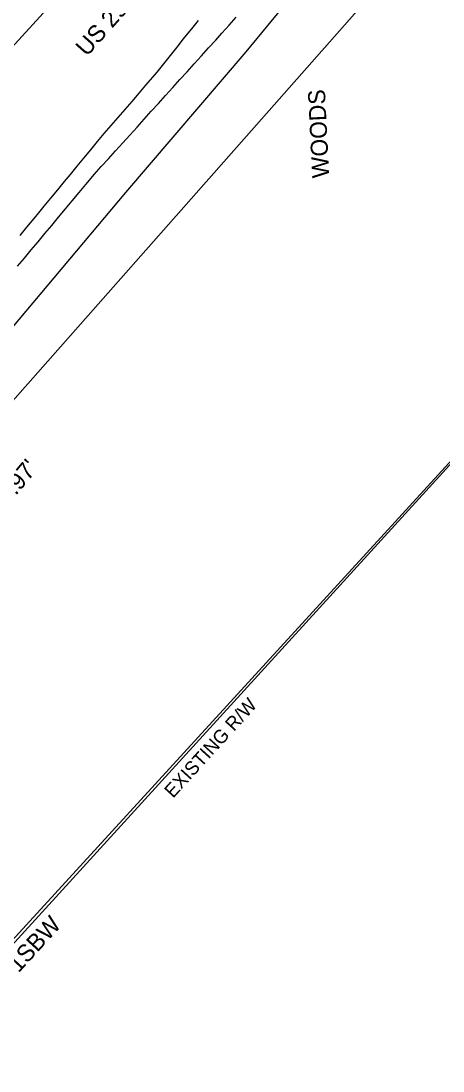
# Model space of a CAD drawing. Extents: x 1806071 to 1809844, y 912722 to 917035.
# Drawn here: x 1808149.9 to 1808248.8, y 914717.3 to 914963.4 of the extents above; entities that cross this region are included whole.
import ezdxf

# ---------------------------------------------------------------- set-up
doc = ezdxf.new("R2010")
doc.units = 0
for name, color, linetype in [('Exist Guardrail', 7, 'Continuous'), ('Exist Other Culture Fence Line', 7, 'Continuous'), ('Exist Other Culture Fence Line Text', 7, 'Continuous'), ('Exist Right of Way Line', 7, 'Continuous'), ('Exist Right of Way Line Text', 7, 'Continuous'), ('Exist Roads EOP', 7, 'Continuous'), ('Exist Roads EOP Text', 7, 'Continuous'), ('Exist Roads EOT', 7, 'Continuous'), ('Exist Structure Minor Pipes RCP 18 Inch Invert', 7, 'Continuous'), ('Exist Vegetation Woods Line', 7, 'Continuous'), ('Exist Vegetation Woods Line Text', 7, 'Continuous')]:
    doc.layers.add(name, color=color, linetype=linetype)

msp = doc.modelspace()

# ---------------------------------------------------------------- linework, layer by layer
at = {"layer": 'Exist Guardrail'}
msp.add_lwpolyline([(1808591.05, 915389.5), (1808569.06, 915365.7), (1808543.65, 915338.5), (1808510.12, 915301.43), (1808476.4, 915264.39), (1808442.71, 915227.63), (1808412.8, 915194.83), (1808379.91, 915158.29), (1808346.06, 915121.3), (1808316.39, 915089.09), (1808287.07, 915056.31), (1808258.76, 915023.41), (1808230.12, 914989.62), (1808202.58, 914956.19), (1808174.39, 914923.17), (1808146.14, 914889.53), (1808117.77, 914855.87), (1808088.77, 914822.19), (1808060.62, 914790.15), (1808030.71, 914757.47), (1808001.37, 914724.91), (1807974.55, 914694.38)], dxfattribs=at)
at = {"layer": 'Exist Other Culture Fence Line'}
msp.add_line((1808258.12, 914868.51), (1807957.39, 914539.49), dxfattribs=at)
at = {"layer": 'Exist Right of Way Line'}
msp.add_line((1808525.76, 915161.65), (1807958.27, 914538.68), dxfattribs=at)
at = {"layer": 'Exist Roads EOP'}
msp.add_lwpolyline([(1808149.15, 914905.88), (1808150.75, 914907.8), (1808152.35, 914909.72), (1808153.95, 914911.64), (1808155.55, 914913.56), (1808157.15, 914915.48), (1808158.75, 914917.41), (1808160.35, 914919.33), (1808161.95, 914921.25), (1808163.55, 914923.17), (1808165.15, 914925.09), (1808166.76, 914927.01), (1808167.06, 914927.38), (1808168.74, 914929.24), (1808170.42, 914931.09), (1808172.09, 914932.95), (1808173.77, 914934.8), (1808175.44, 914936.66), (1808177.12, 914938.51), (1808178.79, 914940.37), (1808180.47, 914942.22), (1808182.14, 914944.08), (1808183.82, 914945.93), (1808185.5, 914947.79), (1808187.17, 914949.65), (1808188.85, 914951.5), (1808190.52, 914953.36), (1808192.2, 914955.21), (1808193.87, 914957.07), (1808195.55, 914958.92), (1808197.02, 914960.56), (1808198.7, 914962.42), (1808200.37, 914964.27)], dxfattribs=at)
at = {"layer": 'Exist Roads EOT'}
msp.add_line((1807617.6, 914375.74), (1808224.93, 915041.78), dxfattribs=at)
msp.add_lwpolyline([(1808149.72, 914913.14), (1808151.32, 914915.06), (1808152.19, 914916.1), (1808153.78, 914918.03), (1808155.37, 914919.96), (1808156.96, 914921.88), (1808158.55, 914923.81), (1808160.15, 914925.74), (1808161.51, 914927.39), (1808163.1, 914929.32), (1808164.69, 914931.25), (1808166.27, 914933.18), (1808167.86, 914935.12), (1808169.4, 914936.99), (1808171.04, 914938.88), (1808172.68, 914940.77), (1808174.31, 914942.66), (1808175.95, 914944.55), (1808177.59, 914946.44), (1808179.22, 914948.33), (1808180.86, 914950.22), (1808181.86, 914951.37), (1808183.41, 914953.33), (1808184.95, 914955.3), (1808186.5, 914957.26), (1808188.04, 914959.23), (1808188.36, 914959.63), (1808189.95, 914961.56), (1808191.54, 914963.49)], dxfattribs=at)
at = {"layer": 'Exist Vegetation Woods Line'}
msp.add_lwpolyline([(1808108.12, 914683.23), (1808099.27, 914714.87), (1808116.08, 914804.21), (1808120.23, 914842.94), (1808559.12, 915340.21), (1808564.92, 915339.58), (1808560.84, 915316.2), (1808513.2, 915243.98), (1808463.81, 915181.71), (1808444.02, 915172.44), (1808388.95, 915106.15), (1808359.09, 915070.98), (1808353.92, 915054.91), (1808362.94, 915036.53), (1808366.74, 915015.13), (1808346.47, 914993.89), (1808341.37, 914946.67)], dxfattribs=at)

# ---------------------------------------------------------------- texts
at = {"layer": 'Exist Other Culture Fence Line Text'}
msp.add_text('48" WW & 1SBW', height=4, rotation=47.5731, dxfattribs=at).set_placement((1808131.83, 914720.96))
at = {"layer": 'Exist Right of Way Line Text'}
msp.add_text('EXISTING R/W', height=3.2, rotation=47.668, dxfattribs=at).set_placement((1808185.57, 914781.08))
at = {"layer": 'Exist Roads EOP Text'}
msp.add_text("US 29 NORTH    38' BST", height=4, rotation=48.4571, dxfattribs=at).set_placement((1808165.37, 914954.88))
at = {"layer": 'Exist Structure Minor Pipes RCP 18 Inch Invert'}
msp.add_text("INV=659.97'", height=4, rotation=50.0202, dxfattribs=at).set_placement((1808135.24, 914835.96))
at = {"layer": 'Exist Vegetation Woods Line Text'}
msp.add_text('WOODS', height=4, rotation=92.8422, dxfattribs=at).set_placement((1808222.17, 914926.66))

doc.saveas('drawing.dxf')
